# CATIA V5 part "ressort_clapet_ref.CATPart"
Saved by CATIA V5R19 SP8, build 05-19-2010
Part number: ressort_clapet_ref
Revision: ANY
Definition: UNKNOWN
Nomenclature: 13
Source: Unknown
Bounding box of the stored display mesh (mm): x -3.775 to 3.907, y -3.709 to 3.84, z -6 to 0
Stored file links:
  D:\Documents\1_Travail\2- 2I2D\1 - Cours et TD\2- TD\3-TD Assemblage\Pompe AirMan\ressort_clapet_ref.CATPart
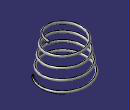
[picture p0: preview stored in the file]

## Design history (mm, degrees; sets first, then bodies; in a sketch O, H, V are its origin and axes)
Body1 "Enlèv. mat.-Extru.2" (main body)
  Solid1: solid without history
